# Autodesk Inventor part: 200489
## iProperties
Created: 2007-11
Part Number: 200489
Document SubType Name: Modeling
Designer: TH
Density: 7.85 g/cm^3
Mass: 170.344 g
Surface Area: 144.32 cm^2
Volume: 21.6998 cm^3
Material: Steel
Description: SIDE PIVOT PLATE
Component Category: Lower Component
Author: TH
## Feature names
1. Extrusion1
2. Extrusion2
3. Chamfer1
4. Mirror1
5. Extrusion3
6. Chamfer2
7. Mirror2
8. Extrusion4
9. Extrusion5
10. Fillet1
11. Circular Pattern1
